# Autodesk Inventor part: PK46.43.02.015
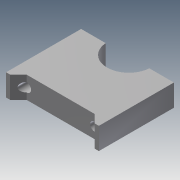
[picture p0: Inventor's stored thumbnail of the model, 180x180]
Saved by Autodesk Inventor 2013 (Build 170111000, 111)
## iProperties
Shininess: 64.0
Length Units: 11269
Angle Units: 11279
Time Units: 11290
Mass Units: 11283
Length Display Precision: 3
Angle Display Precision: 2
Compacted: True
Part Number: PK46.43.02.015
Document SubType Name: Modeling
Created: 2004-12
Material: Steel, High Strength Low Alloy
Designer: ELarisa
Manufacturer: Standard
Standards Organization: Custom
Density: 7.84 g/cm^3
Density: 0.0
Volumn: 0.0
Area: 0.0
PropertySet Name: Model Information
Control State: 0
Master: False
Checked Out: False
Checked Out Date: 2008-10-09
Last Check In Date: 2008-10-09
Author: ELarisa
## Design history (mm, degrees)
sketch "Эскиз1"
  geometry: L1 (-26.065, -28.063)-(-26.065, 26.937); L2 (41.935, 26.937)-(41.935, -28.063); L3 (7.935, 36.963)-(7.935, -16.079); L4 (41.935, -28.063)-(38.935, -28.063); L5 (-23.065, -28.063)-(-26.065, -28.063); L6 (-26.065, 26.937)-(-8.034, 26.937); L7 (23.904, 26.937)-(41.935, 26.937); L8 (-23.065, -28.063)-(-17.065, -22.063); L9 (-17.065, -22.063)-(32.935, -22.063); L10 (32.935, -22.063)-(38.935, -28.063); A1 r 16 centre (7.935, 27.937) between (-8.034, 26.937) and (23.904, 26.937)
  constraints: 20 end point, 6 parallel, 5 perpendicular, 2 point on circle, 1 centre point, 1 collinear, 1 point on line, 1 vertical, 1 other
  dimensions: "d0" = 55 distance of L1.start L1.end; "d1" = 68 distance of L1.end L2.start; "d2" = 34 distance from line of L1 A1.centre; "d6" = 32 diameter of A1; "d20" = 1 distance from line of L7 A1.centre; "d21" = 55 distance of L2.start L2.end (= d0); "d23" = 6 distance between parallel lines of L9 L5; "d24" = 50 distance of L9.end L8.end; "d25" = 25 distance from line of L3 L8.end (= 0.5 x d24); "d26" = 135 deg angle of L8 L5
extrude "Выдавливание1" new body sketch "Эскиз1" distance "d7" = 16; taper "d8" = 0 deg
sketch "Эскиз2"
  geometry: L1 (-49.969, 0)-(-49.969, -16) reference; L2 (-49.969, -16)-(-31.937, -16) reference; L3 (-31.937, 0)-(-31.937, -16) reference; L4 (-49.969, 0)-(-31.937, 0) reference; 2 further points
  dimensions: "d9" = 50 distance of point (9.031, -8) point (-40.969, -8); "d10" = 8 distance from line of L2 point (-40.969, -8); "d11" = 9 distance from line of L1 point (-40.969, -8); "d12" = 0 vertical distance of point (9.031, -8) point (-40.969, -8)
hole "Отверстие1" sketch "Эскиз2" diameter "d13" = 6.647; stored, may be unused: countersink angle "d17" = 82 deg, drill point angle "d19" = 118 deg; dims "d14" = 20, "d15" = 11.2, "d16" = 2, "d18" = 8
body "Solid1"
other parameters: "d3" = 1, "d5" = 74
